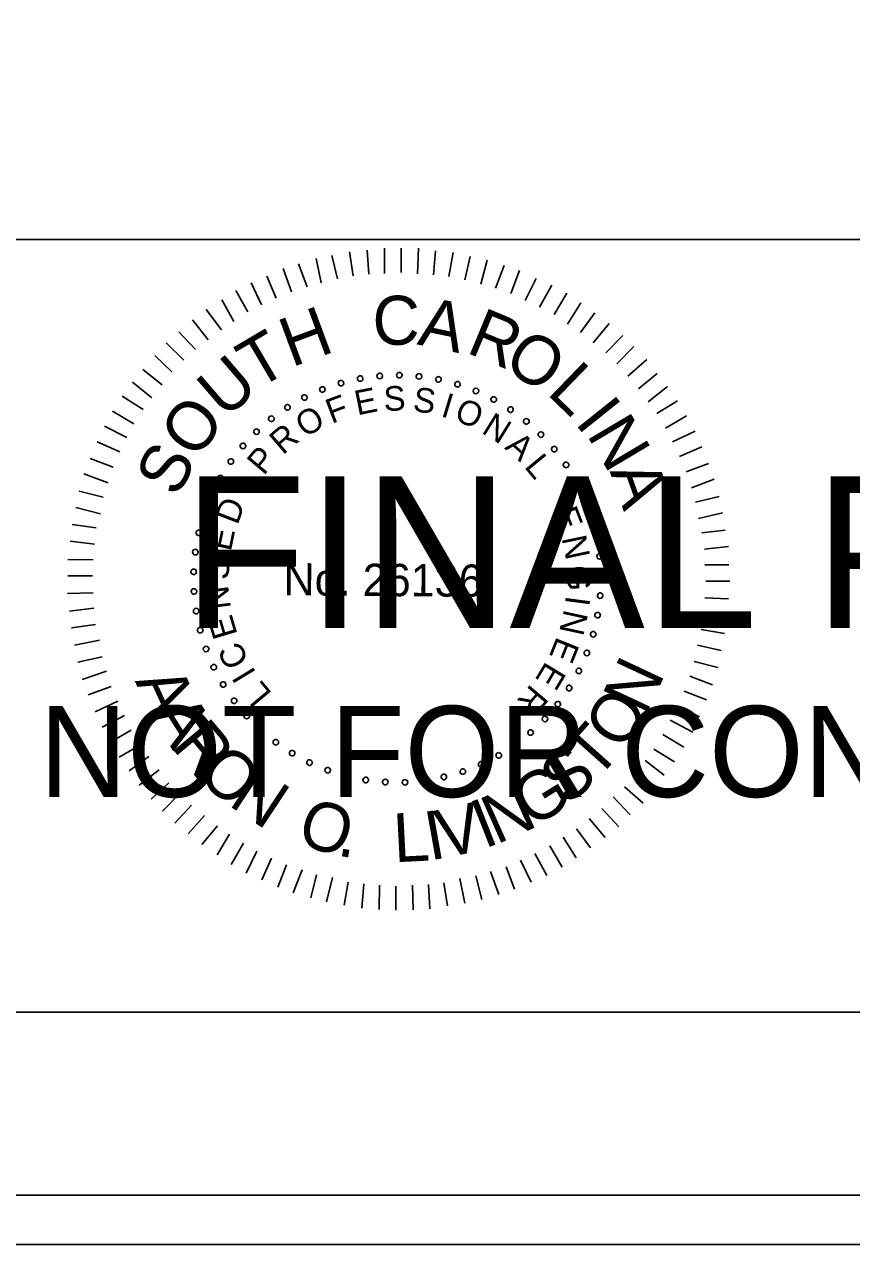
# Model space of a CAD drawing. Extents: x 967 to 1326, y 964 to 2864.
# Drawn here: x 1170.56 to 1189.3, y 963.72 to 991.36 of the extents above; entities that cross this region are included whole.
import ezdxf

# ---------------------------------------------------------------- set-up
doc = ezdxf.new("R2010")
doc.units = 0
for name, color, linetype in [('RD_PD_Final_TX', 7, 'Continuous'), ('RD_XS_TX_Elev_PR', 7, 'Continuous'), ('RD_XS_TX_Misc', 7, 'Continuous'), ('RD_XS_TX_ShdSlope', 7, 'Continuous')]:
    doc.layers.add(name, color=color, linetype=linetype)

msp = doc.modelspace()

# ---------------------------------------------------------------- linework, layer by layer
at = {"layer": 'RD_PD_Final_TX'}
for p, q in [((996.114, 986.486), (1323.886, 986.486)), ((1323.886, 968.983), (996.114, 968.983))]:
    msp.add_line(p, q, dxfattribs=at)
at = {"layer": 'RD_XS_TX_Elev_PR'}
for points in [[(967.409, 963.72), (1326.285, 963.72), (1326.285, 1183.72), (967.409, 1183.72)], [(988.525, 964.84), (1326.285, 964.84), (1326.285, 1182.6), (988.525, 1182.6)]]:
    msp.add_lwpolyline(points, close=True, dxfattribs=at)
at = {"layer": 'RD_XS_TX_ShdSlope'}
for p, q in [((1178.01, 985.663), (1177.93, 986.209)), ((1178.364, 985.699), (1178.33, 986.244)), ((1178.717, 985.719), (1178.722, 986.295)), ((1179.093, 985.739), (1179.098, 986.292)), ((1179.469, 985.713), (1179.489, 986.288)), ((1179.829, 985.687), (1179.872, 986.231)), ((1180.174, 985.646), (1180.271, 986.19)), ((1176.964, 985.419), (1176.769, 985.935)), ((1177.287, 985.508), (1177.169, 986.054)), ((1177.657, 985.597), (1177.53, 986.128)), ((1180.535, 985.573), (1180.662, 986.102)), ((1180.902, 985.478), (1181.045, 986.022)), ((1176.264, 985.156), (1176.053, 985.657)), ((1176.61, 985.306), (1176.423, 985.83)), ((1181.231, 985.384), (1181.428, 985.896)), ((1181.584, 985.265), (1181.78, 985.786)), ((1175.933, 985.005), (1175.699, 985.506)), ((1181.905, 985.109), (1182.154, 985.606)), ((1182.226, 984.953), (1182.506, 985.45)), ((1175.308, 984.634), (1175.036, 985.12)), ((1175.624, 984.846), (1175.352, 985.332)), ((1182.562, 984.789), (1182.85, 985.27)), ((1175.03, 984.445), (1174.681, 984.9)), ((1182.86, 984.572), (1183.163, 985.053)), ((1183.158, 984.378), (1183.484, 984.828)), ((1174.729, 984.217), (1174.372, 984.665)), ((1183.447, 984.145), (1183.811, 984.587)), ((1174.435, 983.997), (1174.062, 984.399)), ((1183.729, 983.92), (1184.116, 984.316)), ((1174.172, 983.753), (1173.776, 984.148)), ((1183.98, 983.672), (1184.368, 984.061)), ((1173.909, 983.479), (1173.52, 983.858)), ((1184.232, 983.394), (1184.657, 983.767)), ((1173.684, 983.197), (1173.242, 983.546)), ((1184.475, 983.108), (1184.892, 983.45)), ((1173.451, 982.9), (1173.009, 983.256)), ((1184.687, 982.807), (1185.128, 983.156)), ((1173.257, 982.64), (1172.776, 982.936)), ((1173.039, 982.312), (1172.559, 982.6)), ((1184.885, 982.544), (1185.355, 982.832)), ((1185.081, 982.213), (1185.56, 982.493)), ((1172.883, 982.006), (1172.379, 982.256)), ((1185.24, 981.904), (1185.756, 982.145)), ((1172.727, 981.677), (1172.215, 981.904)), ((1185.399, 981.573), (1185.907, 981.791)), ((1172.571, 981.333), (1172.051, 981.53)), ((1185.549, 981.226), (1186.057, 981.414)), ((1172.461, 980.974), (1171.91, 981.178)), ((1185.669, 980.865), (1186.185, 981.06)), ((1172.351, 980.652), (1171.807, 980.787)), ((1185.759, 980.541), (1186.297, 980.667)), ((1172.286, 980.276), (1171.727, 980.419)), ((1185.832, 980.165), (1186.371, 980.298)), ((1172.191, 979.955), (1171.647, 980.029)), ((1185.906, 979.842), (1186.436, 979.906)), ((1172.15, 979.587), (1171.598, 979.653)), ((1185.964, 979.473), (1186.51, 979.53)), ((1172.124, 979.234), (1171.548, 979.239)), ((1185.977, 979.12), (1186.514, 979.115)), ((1172.105, 978.866), (1171.545, 978.871)), ((1185.997, 978.751), (1186.542, 978.747)), ((1172.118, 978.482), (1171.542, 978.471)), ((1185.971, 978.368), (1186.508, 978.348)), ((1172.138, 978.136), (1171.585, 978.072)), ((1185.952, 978.022), (1186.497, 977.949)), ((1172.173, 977.768), (1171.627, 977.688)), ((1185.888, 977.655), (1186.417, 977.566)), ((1172.262, 977.414), (1171.701, 977.296)), ((1185.808, 977.302), (1186.345, 977.175)), ((1172.321, 977.037), (1171.774, 976.911)), ((1185.729, 976.926), (1186.265, 976.792)), ((1172.425, 976.707), (1171.871, 976.519)), ((1185.634, 976.597), (1186.146, 976.401)), ((1172.53, 976.36), (1172.007, 976.173)), ((1185.508, 976.253), (1186.013, 976.057)), ((1172.681, 976.029), (1172.165, 975.788)), ((1172.831, 975.705), (1172.323, 975.441)), ((1185.352, 975.924), (1185.857, 975.675)), ((1185.188, 975.603), (1185.7, 975.33)), ((1172.982, 975.374), (1172.497, 975.094)), ((1185.024, 975.274), (1185.498, 974.987)), ((1173.194, 975.042), (1172.709, 974.762)), ((1184.822, 974.946), (1185.288, 974.658)), ((1173.384, 974.78), (1172.936, 974.453)), ((1184.62, 974.687), (1185.055, 974.353)), ((1173.612, 974.478), (1173.164, 974.129)), ((1184.403, 974.389), (1184.814, 974.033)), ((1173.832, 974.177), (1173.437, 973.812)), ((1184.155, 974.092), (1184.574, 973.72)), ((1174.091, 973.945), (1173.689, 973.541)), ((1183.899, 973.864), (1184.28, 973.454)), ((1174.35, 973.674), (1173.97, 973.263)), ((1183.644, 973.597), (1184.024, 973.18)), ((1174.64, 973.442), (1174.275, 973.022)), ((1174.937, 973.209), (1174.58, 972.782)), ((1183.358, 973.37), (1183.715, 972.944)), ((1175.212, 973.014), (1174.932, 972.549)), ((1182.764, 972.952), (1183.059, 972.482)), ((1183.065, 973.141), (1183.384, 972.709)), ((1175.525, 972.812), (1175.245, 972.331)), ((1182.463, 972.755), (1182.743, 972.269)), ((1175.83, 972.633), (1175.588, 972.136)), ((1176.159, 972.477), (1175.94, 971.98)), ((1181.8, 972.431), (1182.041, 971.93)), ((1182.124, 972.581), (1182.396, 972.08)), ((1176.503, 972.321), (1176.307, 971.816)), ((1176.855, 972.211), (1176.651, 971.69)), ((1177.177, 972.1), (1177.05, 971.572)), ((1181.122, 972.175), (1181.31, 971.652)), ((1181.476, 972.28), (1181.664, 971.771)), ((1177.545, 972.036), (1177.409, 971.484)), ((1177.897, 971.933), (1177.808, 971.412)), ((1178.25, 971.892), (1178.207, 971.34)), ((1178.603, 971.866), (1178.598, 971.313)), ((1178.978, 971.84), (1178.974, 971.295)), ((1179.355, 971.86), (1179.365, 971.307)), ((1179.715, 971.88), (1179.749, 971.327)), ((1180.061, 971.915), (1180.149, 971.393)), ((1180.423, 972.012), (1180.541, 971.458)), ((1180.791, 972.07), (1180.926, 971.54))]:
    msp.add_line(p, q, dxfattribs=at)
for centre, start, end in [((1178.609, 983.397), 5.0653, 185.0653), ((1179.055, 983.414), 359.5268, 179.5268), ((1179.5, 983.388), 353.9884, 173.9884), ((1177.312, 983.091), 21.6807, 201.6807), ((1177.734, 983.235), 16.1422, 196.1422), ((1177.734, 983.235), 196.1422, 16.1422), ((1178.168, 983.337), 10.6038, 190.6038), ((1178.168, 983.337), 190.6038, 10.6038), ((1178.609, 983.397), 185.0653, 5.0653), ((1179.055, 983.414), 179.5268, 359.5268), ((1179.5, 983.388), 173.9884, 353.9884), ((1179.94, 983.319), 168.4499, 348.4499), ((1179.94, 983.319), 348.4499, 168.4499), ((1180.372, 983.208), 162.9114, 342.9114), ((1180.372, 983.208), 342.9114, 162.9114), ((1176.906, 982.908), 27.2191, 207.2191), ((1176.906, 982.908), 207.2191, 27.2191), ((1177.312, 983.091), 201.6807, 21.6807), ((1180.79, 983.056), 157.373, 337.373), ((1180.79, 983.056), 337.373, 157.373), ((1181.193, 982.864), 151.8345, 331.8345), ((1181.193, 982.864), 331.8345, 151.8345), ((1176.52, 982.686), 32.7576, 212.7576), ((1176.52, 982.686), 212.7576, 32.7576), ((1181.574, 982.634), 146.2961, 326.2961), ((1181.574, 982.634), 326.2961, 146.2961), ((1176.156, 982.428), 38.2961, 218.2961), ((1176.156, 982.428), 218.2961, 38.2961), ((1181.932, 982.368), 140.7576, 320.7576), ((1181.932, 982.368), 320.7576, 140.7576), ((1175.82, 982.135), 43.8345, 223.8345), ((1175.82, 982.135), 223.8345, 43.8345), ((1182.263, 982.069), 135.2191, 315.2191), ((1182.263, 982.069), 315.2191, 135.2191), ((1175.513, 981.812), 49.373, 229.373), ((1175.513, 981.812), 229.373, 49.373), ((1182.563, 981.74), 129.6807, 309.6807), ((1182.563, 981.74), 309.6807, 129.6807), ((1175.239, 981.461), 54.9114, 234.9114), ((1175.239, 981.461), 234.9114, 54.9114), ((1182.83, 981.383), 124.1422, 304.1422), ((1182.83, 981.383), 304.1422, 124.1422), ((1175, 981.085), 60.4499, 240.4499), ((1175, 981.085), 240.4499, 60.4499), ((1183.061, 981.002), 118.6038, 298.6038), ((1183.061, 981.002), 298.6038, 118.6038), ((1174.798, 980.687), 65.9884, 245.9884), ((1174.798, 980.687), 245.9884, 65.9884), ((1183.255, 980.601), 293.0653, 113.0653), ((1183.255, 980.601), 113.0653, 293.0653), ((1174.636, 980.272), 71.5268, 251.5268), ((1174.636, 980.272), 251.5268, 71.5268), ((1183.408, 980.182), 107.5268, 287.5268), ((1183.408, 980.182), 287.5268, 107.5268), ((1174.514, 979.843), 77.0653, 257.0653), ((1174.514, 979.843), 257.0653, 77.0653), ((1183.521, 979.751), 101.9884, 281.9884), ((1183.521, 979.751), 281.9884, 101.9884), ((1174.435, 979.405), 82.6038, 262.6038), ((1174.435, 979.405), 262.6038, 82.6038), ((1183.592, 979.311), 96.4499, 276.4499), ((1183.592, 979.311), 276.4499, 96.4499), ((1174.398, 978.961), 88.1422, 268.1422), ((1174.398, 978.961), 268.1422, 88.1422), ((1183.619, 978.866), 90.9114, 270.9114), ((1183.619, 978.866), 270.9114, 90.9114), ((1174.404, 978.515), 93.6807, 273.6807), ((1174.404, 978.515), 273.6807, 93.6807), ((1183.604, 978.421), 85.373, 265.373), ((1183.604, 978.421), 265.373, 85.373), ((1174.453, 978.072), 99.2191, 279.2191), ((1174.453, 978.072), 279.2191, 99.2191), ((1183.546, 977.979), 79.8345, 259.8345), ((1183.546, 977.979), 259.8345, 79.8345), ((1174.545, 977.636), 104.7576, 284.7576), ((1174.545, 977.636), 284.7576, 104.7576), ((1183.445, 977.545), 74.2961, 254.2961), ((1183.445, 977.545), 254.2961, 74.2961), ((1174.678, 977.211), 110.2961, 290.2961), ((1174.678, 977.211), 290.2961, 110.2961), ((1183.303, 977.122), 68.7576, 248.7576), ((1183.303, 977.122), 248.7576, 68.7576), ((1174.852, 976.8), 115.8345, 295.8345), ((1174.852, 976.8), 295.8345, 115.8345), ((1183.121, 976.716), 63.2191, 243.2191), ((1183.121, 976.716), 243.2191, 63.2191), ((1175.065, 976.409), 121.373, 301.373), ((1175.065, 976.409), 301.373, 121.373), ((1182.9, 976.328), 57.6807, 237.6807), ((1182.9, 976.328), 237.6807, 57.6807), ((1175.314, 976.039), 126.9114, 306.9114), ((1175.314, 976.039), 306.9114, 126.9114), ((1182.643, 975.964), 52.1422, 232.1422), ((1182.643, 975.964), 232.1422, 52.1422), ((1175.598, 975.696), 132.4499, 312.4499), ((1175.598, 975.696), 312.4499, 132.4499), ((1182.353, 975.627), 46.6038, 226.6038), ((1175.914, 975.381), 137.9884, 317.9884), ((1175.914, 975.381), 317.9884, 137.9884), ((1182.353, 975.627), 226.6038, 46.6038), ((1176.258, 975.099), 143.5268, 323.5268), ((1176.258, 975.099), 323.5268, 143.5268), ((1182.03, 975.319), 41.0653, 221.0653), ((1182.03, 975.319), 221.0653, 41.0653), ((1176.629, 974.851), 149.0653, 329.0653), ((1176.629, 974.851), 329.0653, 149.0653), ((1181.305, 974.803), 29.9884, 209.9884), ((1181.68, 975.043), 35.5268, 215.5268), ((1181.68, 975.043), 215.5268, 35.5268), ((1177.021, 974.639), 154.6038, 334.6038), ((1177.021, 974.639), 334.6038, 154.6038), ((1180.908, 974.6), 24.4499, 204.4499), ((1180.908, 974.6), 204.4499, 24.4499), ((1181.305, 974.803), 209.9884, 29.9884), ((1177.432, 974.467), 160.1422, 340.1422), ((1177.432, 974.467), 340.1422, 160.1422), ((1177.858, 974.335), 165.6807, 345.6807), ((1177.858, 974.335), 345.6807, 165.6807), ((1178.294, 974.245), 351.2191, 171.2191), ((1180.065, 974.313), 13.373, 193.373), ((1180.065, 974.313), 193.373, 13.373), ((1180.494, 974.436), 18.9114, 198.9114), ((1180.494, 974.436), 198.9114, 18.9114), ((1178.294, 974.245), 171.2191, 351.2191), ((1178.737, 974.198), 356.7576, 176.7576), ((1178.737, 974.198), 176.7576, 356.7576), ((1179.183, 974.193), 2.2961, 182.2961), ((1179.183, 974.193), 182.2961, 2.2961), ((1179.627, 974.232), 7.8345, 187.8345), ((1179.627, 974.232), 187.8345, 7.8345)]:
    msp.add_arc(centre, 0.0627, start, end, dxfattribs=at)

# ---------------------------------------------------------------- texts
at = {"layer": 'RD_XS_TX_Misc'}
for s, height, p in [('FINAL PLANS', 3.4375, (1174.145, 977.685)), ('NOT FOR CONSTRUCTION', 2.0625, (1170.901, 973.86))]:
    msp.add_text(s, height=height, dxfattribs=at).set_placement(p)
at = {"layer": 'RD_XS_TX_ShdSlope'}
for s, height, rotation, p in [('C', 1.11, 359.5482, (1178.442, 984.108)), ('A', 1.11, 348.1981, (1179.439, 984.115)), ('H', 1.11, 20.3637, (1176.614, 983.587)), ('R', 1.11, 337.4344, (1180.541, 983.937)), ('T', 1.11, 30.4992, (1175.828, 983.072)), ('O', 1.108, 326.5869, (1181.366, 983.609)), ('U', 1.11, 40.8022, (1175.102, 982.403)), ('L', 1.11, 315.9488, (1182.373, 983.003)), ('S', 0.557, 2.208, (1178.709, 982.601)), ('F', 0.557, 20.6127, (1177.52, 982.309)), ('E', 0.557, 11.4103, (1178.103, 982.503)), ('S', 0.557, 352.6608, (1179.346, 982.599)), ('I', 0.557, 343.1136, (1179.975, 982.491)), ('I', 1.11, 308.6613, (1183.011, 982.338)), ('O', 1.11, 52.0267, (1174.435, 981.474)), ('O', 0.557, 30.8477, (1176.917, 981.987)), ('O', 0.557, 338.4392, (1180.274, 982.401)), ('N', 0.557, 328.2042, (1180.896, 982.12)), ('N', 1.11, 300.7037, (1183.285, 982.075)), ('R', 0.557, 40.3949, (1176.415, 981.594)), ('A', 0.557, 318.657, (1181.424, 981.762)), ('S', 1.108, 63.2511, (1174.029, 980.619)), ('P', 0.557, 49.9421, (1175.985, 981.124)), ('L', 0.557, 309.4546, (1181.869, 981.339)), ('A', 1.11, 289.4792, (1183.814, 981.243)), ('D', 0.557, 69.0364, (1175.386, 980.003)), ('E', 0.557, 291.049, (1182.53, 980.307)), ('E', 0.557, 78.2388, (1175.238, 979.407)), ('N', 0.557, 281.8466, (1182.728, 979.726)), ('S', 0.557, 87.786, (1175.187, 978.772)), ('No. 26136', 0.7311, 359.5268, (1176.429, 978.43)), ('G', 0.557, 272.2995, (1182.833, 979.097)), ('N', 0.557, 97.3332, (1175.242, 978.137)), ('I', 0.557, 262.4084, (1182.83, 978.437)), ('E', 0.557, 106.5355, (1175.394, 977.541)), ('N', 0.557, 257.7339, (1182.789, 978.127)), ('E', 0.557, 248.1867, (1182.628, 977.511)), ('C', 0.557, 116.4266, (1175.661, 976.938)), ('E', 0.557, 238.9844, (1182.378, 976.949)), ('N', 1.105, 64.8922, (1184.632, 975.684)), ('A', 1.105, 294.7297, (1173.062, 976.486)), ('I', 0.557, 121.1011, (1175.823, 976.67)), ('L', 0.557, 129.9595, (1176.187, 976.204)), ('R', 0.557, 229.782, (1182.041, 976.435)), ('O', 1.105, 56.2059, (1184.102, 974.874)), ('A', 1.105, 302.2892, (1173.414, 975.72)), ('R', 1.105, 309.8487, (1173.865, 975.007)), ('T', 1.105, 48.2685, (1183.515, 974.211)), ('O', 1.105, 317.7861, (1174.434, 974.33)), ('S', 1.105, 40.3311, (1182.842, 973.636)), ('N', 1.105, 326.4725, (1175.158, 973.686)), ('G', 1.105, 32.0198, (1182.059, 973.14)), ('N', 1.105, 24.0824, (1181.252, 972.776)), ('O', 1.105, 342.3472, (1176.697, 972.82)), ('V', 1.105, 12.7741, (1180.033, 972.457)), ('I', 1.105, 21.4605, (1180.976, 972.681)), ('L', 1.105, 2.9677, (1178.943, 972.379)), ('I', 1.105, 10.1523, (1179.743, 972.418)), ('.', 1.105, 351.0336, (1177.623, 972.536))]:
    msp.add_text(s, height=height, rotation=rotation, dxfattribs=at).set_placement(p)

doc.saveas('drawing.dxf')
